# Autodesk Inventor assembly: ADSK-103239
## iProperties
Shininess: 0.0
Created: 2000-11
Part Number: ADSK-103239
Document SubType Name: Assembly
Stock Number: ADSK-103239
Density: 0.0
Volumn: 0.0
Area: 0.0
PropertySet Name: Model Information
Control State: 0
Master: False
Checked Out: False
Author: gao
